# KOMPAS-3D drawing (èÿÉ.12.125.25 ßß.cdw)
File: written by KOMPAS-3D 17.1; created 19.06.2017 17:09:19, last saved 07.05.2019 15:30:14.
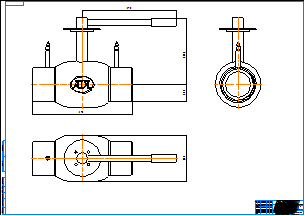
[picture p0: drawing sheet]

Sheet 1: A0, landscape

Title block, sheet 1: name: КШР.12.125.25 сс; material: Внимание! Данный продукт является объектом авторского права ООО «Торговый Дом АДЛ». / Запрещается изменение, копирование, распространение / (в том числе путем копирования на другие сайты и ресурсы в Интернете) / или любое иное использование информации и объектов без предварительного / согласия правообладателя (ООО «Торговый Дом АДЛ»).; scale: 1:1; sheets: 1; organisation: ООО "Торговый дом АДЛ"; sheet format: A0; stored path: C:\Users\tra\Desktop\2д чертежи\Шаровые краны БИВАЛ\КШР_Бивал_серия_12\KOMPAS 2D\КШР.12.125.25 сс.cdw

Views: Спереди 1, Проекционный вид 2, Проекционный вид 3
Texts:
  Klimkovich
  ADL
Dimensions and other numbers on the sheet: 390; 370; 258,4; 66,5; 180; 1:1; 1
